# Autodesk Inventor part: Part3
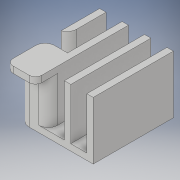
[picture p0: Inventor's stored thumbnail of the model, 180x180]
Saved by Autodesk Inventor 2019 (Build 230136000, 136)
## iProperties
Created: 2019-02
Part Number: Part3
Material: Generic
Document SubType Name: Modeling
Designer: Patel Family
Density: 1 g/cm^3
Appearance: Default
Author: Patel Family
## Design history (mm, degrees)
sketch "Sketch1"
  geometry: L1 (0, 0)-(11.5, 0); L2 (11.5, 0)-(11.5, 12.5); L3 (11.5, 12.5)-(0, 12.5); L4 (0, 12.5)-(0, 0)
  constraints: 8 end point, 2 parallel, 1 horizontal, 1 perpendicular
  dimensions: "d0" = 11.5 distance of L3.end L2.end; "d1" = 12.5 distance of L2.end L1.end
extrude "Extrusion1" new body sketch "Sketch1" distance "d2" = 1; taper "d3" = 0 deg
sketch "Sketch2"
  geometry: L1 (0, -12.5)-(-1, -12.5); L2 (-11.5, -12.5)-(0, -12.5) reference; L3 (-1, -12.5)-(-3.5, -12.5); L4 (-3.5, -12.5)-(-4.5, -12.5); L5 (-4.5, -12.5)-(-7, -12.5); L6 (-7, -12.5)-(-8, -12.5); L7 (-8, -12.5)-(-10.5, -12.5); L8 (-10.5, -12.5)-(-11.5, -12.5); L9 (0, -12.5)-(-1, -12.5); L10 (-1, -12.5)-(-1, 0); L11 (-1, 0)-(0, 0); L12 (0, 0)-(0, -12.5); L13 (-3.5, -12.5)-(-4.5, -12.5); L14 (-4.5, -12.5)-(-4.5, 0); L15 (-4.5, 0)-(-3.5, 0); L16 (-3.5, 0)-(-3.5, -12.5); L17 (-7, -12.5)-(-8, -12.5); L18 (-8, 0)-(-7, 0); L19 (-7, 0)-(-7, -12.5); L20 (-11.5, -12.5)-(-10.5, -12.5); L21 (-10.5, 0)-(-11.5, 0); L22 (-8, -12.5)-(-11.5, -12.5); L23 (-11.5, -12.5)-(-11.5, -8.5); L24 (-11.5, -8.5)-(-8, -8.5); L25 (-11.5, 0)-(-10.5, 0); L26 (-10.5, 0)-(-10.5, -6); L27 (-10.5, -6)-(-11.5, -6); L28 (-11.5, -6)-(-11.5, 0); L29 (-8, 0)-(-8, -8.5); 2 further points
  constraints: 56 end point, 10 parallel, 8 point on line, 6 horizontal, 4 perpendicular, 1 collinear, 2 other
  dimensions: "d4" = 1 distance of L1.start L1.end; "d5" = 2.5 distance of L1.end L3.end; "d6" = 1 distance of L3.end L4.end; "d7" = 2.5 distance of L4.end L5.end; "d8" = 1 distance of L5.end L6.end; "d9" = 2.5 distance of L6.end L7.end; "d10" = 1 distance of L7.end L2.start (derived); "d11" = 4 distance of L22.end L23.end; "d12" = 6 distance of L25.end L26.end
extrude "Extrusion2" join sketch "Sketch2" distance "d13" = 8; taper "d14" = 0 deg
sketch "Sketch3"
  geometry: L1 (0, 0)-(0, 9) reference; L2 (4.5, 1)-(4.5, 9) reference; L3 (0, 9)-(4.5, 9); L4 (4.5, 9)-(4.5, 8); L5 (4.5, 8)-(0, 8); L6 (0, 8)-(0, 9); 1 further point
  constraints: 8 end point, 2 parallel, 1 horizontal, 1 perpendicular, 1 point on line
  dimensions: "d15" = 1 distance of L3.end L4.end
extrude "Extrusion3" join sketch "Sketch3" distance "d16" = 2; taper "d17" = 0 deg
fillet "Fillet1" dims "d18" = 1.5
fillet "Fillet2" dims "d19" = 1
body "Solid1"
